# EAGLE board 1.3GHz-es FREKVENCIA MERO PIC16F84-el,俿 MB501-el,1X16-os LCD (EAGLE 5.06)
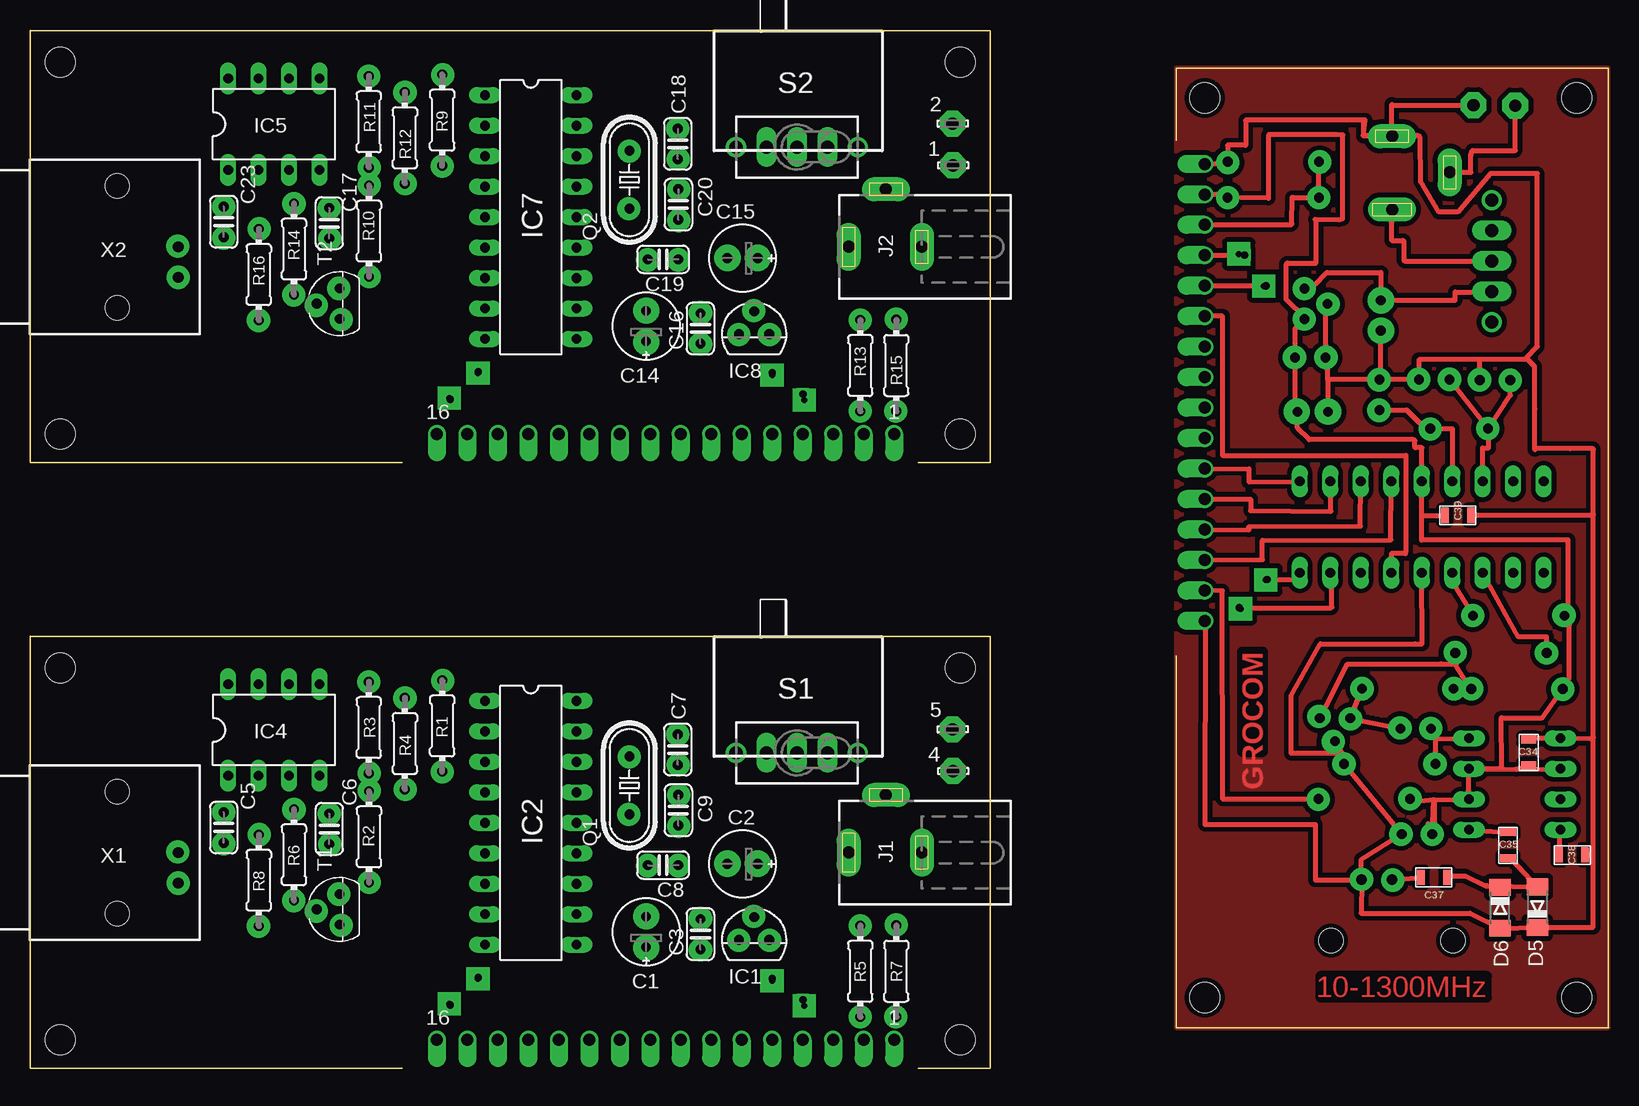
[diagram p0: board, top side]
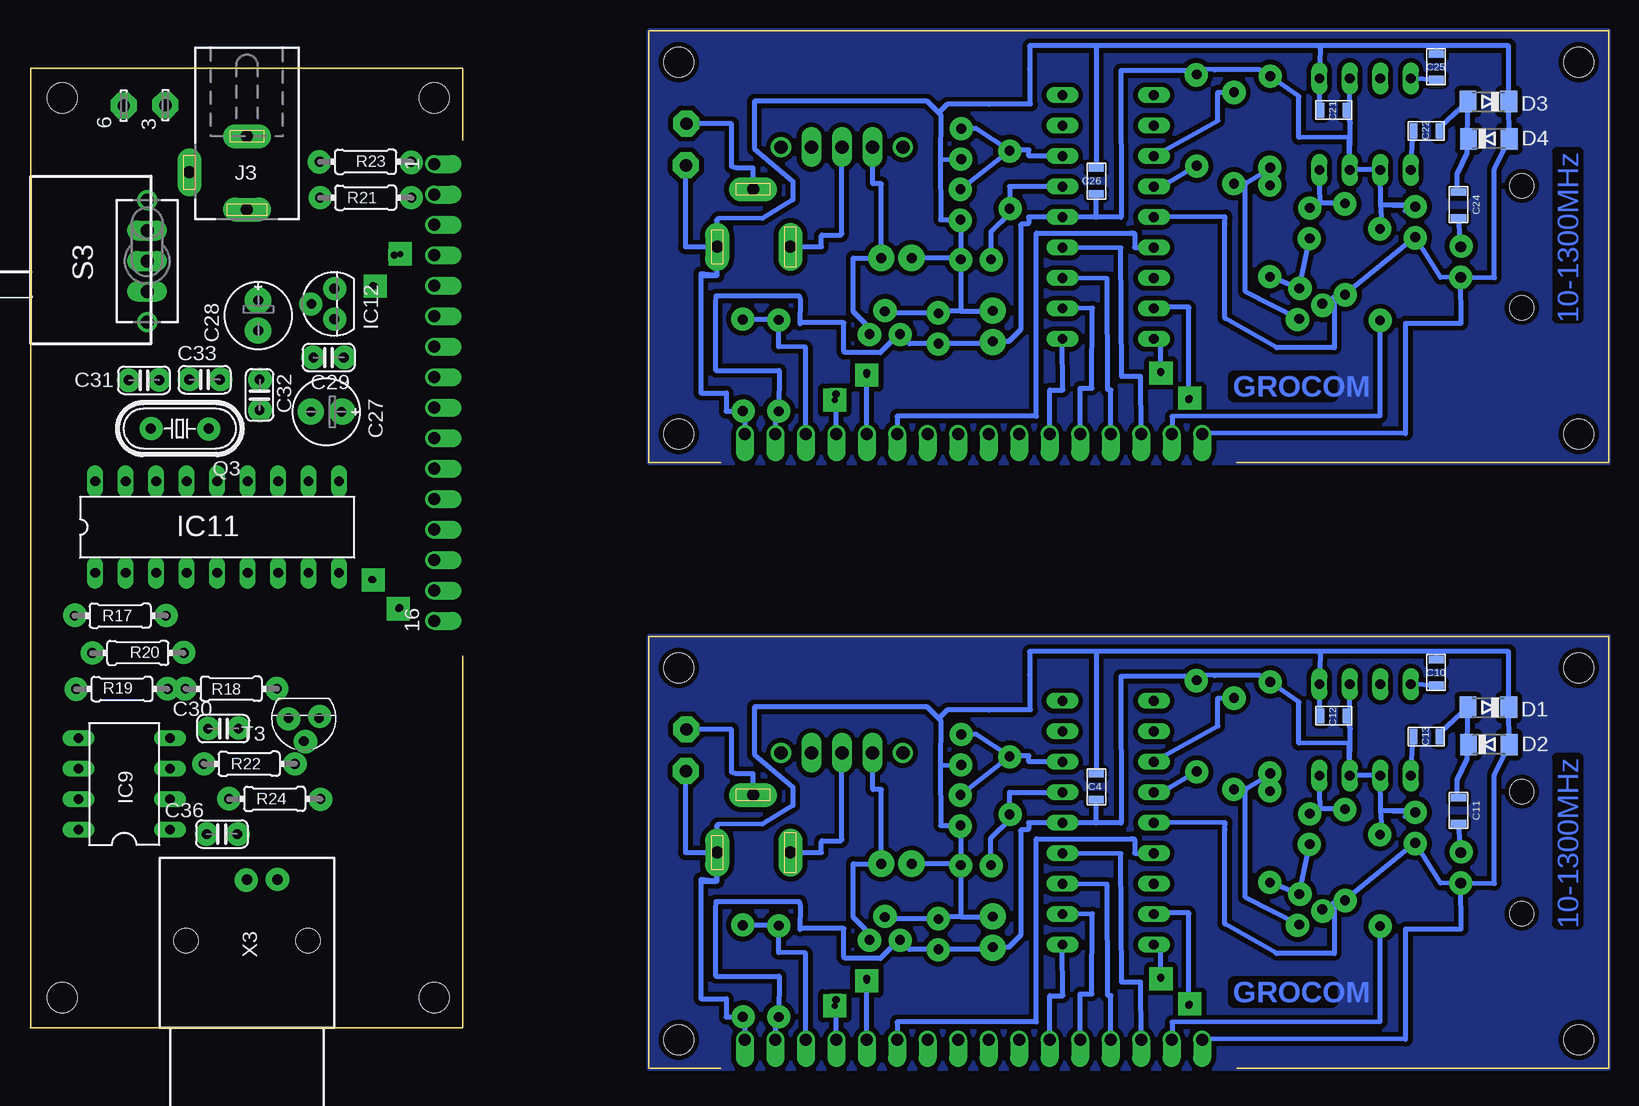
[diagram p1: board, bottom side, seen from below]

Size 131.58 x 86.58 mm. Coordinates in mm from the lower left corner, seen from the top.
Outline: 0,36 0,36.08 0,0
Outline: 0,36 0,0
Outline: 0,36 80,36 80,0 74,0
Outline: 0,0 31,0
Outline: 0,86.5 0,86.58 0,50.5
Outline: 0,86.5 0,50.5
Outline: 0,86.5 80,86.5 80,50.5 74,50.5
Outline: 0,50.5 31,50.5
Outline: 131.5,3.4 131.58,3.4 95.5,3.4
Outline: 131.5,3.4 95.5,3.4
Outline: 131.5,3.4 131.5,83.4 95.5,83.4 95.5,77.4
Outline: 95.5,3.4 95.5,34.4
Copper layers (1*16): Top 0.035mm / dielectric 1.5mm / Bottom 0.035mm
Design rules "default *": minimum track width 10mil, minimum drill 24mil, track to track 8mil, track to pad 8mil, pad to pad 8mil, via to via 8mil, smd to smd 8mil, copper to edge 0mil, drill to drill 8mil, minimum pad ring 10mil, minimum via ring 8mil, stop-mask expansion 4mil, vias tented up to drill 0mil, thermal gap 10mil

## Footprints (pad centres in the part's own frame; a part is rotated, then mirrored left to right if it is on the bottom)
LSP10 = drill 1.016 pad 2.159 octagon: MP 0,0
E2,5-6E = drill 0.813 pad 1.575 round: + -1.27,0 | drill 0.813 pad 1.575 octagon: - 1.27,0
C025-024X044 = drill 0.813 octagon: 1 -1.27,0; 2 1.27,0
0805 = smd 0.635 x 1.27: P$1 1.143,0; P$2 -1.016,0
MINIMELF = smd 1.4 x 1.8: A 1.7,0; C -1.7,0
TO92 = drill 0.813 octagon: 1 -1.27,0; 2 0,1.905; 3 1.27,0
DIL18 = drill 0.813 long: 1 -10.16,-3.81; 2 -7.62,-3.81; 3 -5.08,-3.81; 4 -2.54,-3.81; 5 0,-3.81; 6 2.54,-3.81; 7 5.08,-3.81; 8 7.62,-3.81; 9 10.16,-3.81; 10 10.16,3.81; 11 7.62,3.81; 12 5.08,3.81; 13 2.54,3.81; 14 0,3.81; 15 -2.54,3.81; 16 -5.08,3.81; 17 -7.62,3.81; 18 -10.16,3.81
DMC-162C = drill 1 offset: 1 8,33.5; 2 10.54,33.5; 3 13.08,33.5; 4 15.62,33.5; 5 18.16,33.5; 6 20.7,33.5; 7 23.24,33.5; 8 25.78,33.5; 9 28.32,33.5; 10 30.86,33.5; 11 33.4,33.5; 12 35.94,33.5; 13 38.48,33.5; 14 41.02,33.5; 15 43.56,33.5; 16 46.1,33.5 | hole 2.5: 2.5,2.5; 77.5,2.5; 77.5,33.5; 2.5,33.5
DIL08 = drill 0.813 long: 1 -3.81,-3.81; 2 -1.27,-3.81; 3 1.27,-3.81; 4 3.81,-3.81; 5 3.81,3.81; 6 1.27,3.81; 7 -1.27,3.81; 8 -3.81,3.81
DCJ0202 = drill 1 pad 2 long: 1 0,3.1; 2 4.8,0; 3 0,-3
HC49/S = drill 0.813 round: 1 -2.413,0; 2 2.413,0
0204/7 = drill 0.813 octagon: 1 -3.81,0; 2 3.81,0
TL3XYO = drill 1.1 pad 1.422 long: 1 -2.54,0; 2 0,0; 3 2.54,0 | drill 1.1 pad 1.676 round: M1 -5.08,0; M2 5.08,0
TO92' = drill 0.813 octagon: 1 1.27,0; 2 0,1.905; 3 -1.27,0
AMP_227161 = drill 0.9 pad 1.27 round: 1 0,-5.08; 2 -2.54,-5.08 | hole 2: -5.08,0; 5.08,0

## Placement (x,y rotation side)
1  BE  [LSP10]  76.92,75.29 0 top
2  BE  [LSP10]  76.88,78.78 0 top
3  BE  [LSP10]  120.29,80.32 90 bottom
4  BE  [LSP10]  76.92,24.79 0 top
5  BE  [LSP10]  76.88,28.28 0 top
6  BE  [LSP10]  123.78,80.28 90 bottom
C1  10uF  [E2,5-6E]  51.34,11.39 90 top
C2  10uF  [E2,5-6E]  59.38,17.06 180 top
C3  100nF  [C025-024X044]  55.87,11.19 90 top
C4  1nF  [0805]  42.72,23.55 270 bottom
C5  1nF  [C025-024X044]  16.14,20.08 90 top
C6  10nF  [C025-024X044]  24.94,19.97 270 top
C7  22pF  [C025-024X044]  53.98,26.58 90 top
C8  22pF  [C025-024X044]  52.76,16.95 180 top
C9  CX  [C025-024X044]  54.03,21.53 90 top
C10  1nF  [0805]  14.4,33.08 270 bottom
C11  1nF  [0805]  12.53,21.56 270 bottom
C12  [0805]  23.01,29.4 0 bottom
C13  1nF  [0805]  15.28,27.67 0 bottom
C14  10uF  [E2,5-6E]  51.34,61.89 90 top
C15  10uF  [E2,5-6E]  59.38,67.56 180 top
C16  100nF  [C025-024X044]  55.87,61.69 90 top
C17  10nF  [C025-024X044]  24.94,70.47 270 top
C18  22pF  [C025-024X044]  53.98,77.08 90 top
C19  22pF  [C025-024X044]  52.76,67.45 180 top
C20  CX  [C025-024X044]  54.03,72.03 90 top
C21  [0805]  23.01,79.9 0 bottom
C22  1nF  [0805]  15.28,78.17 0 bottom
C23  1nF  [C025-024X044]  16.14,70.58 90 top
C24  1nF  [0805]  12.53,72.06 270 bottom
C25  1nF  [0805]  14.4,83.58 270 bottom
C26  1nF  [0805]  42.72,74.05 270 bottom
C27  10uF  [E2,5-6E]  106.89,54.74 180 bottom
C28  10uF  [E2,5-6E]  112.56,62.78 270 bottom
C29  100nF  [C025-024X044]  106.69,59.27 180 bottom
C30  10nF  [C025-024X044]  115.47,28.34 0 bottom
C31  22pF  [C025-024X044]  122.08,57.38 180 bottom
C32  22pF  [C025-024X044]  112.45,56.16 270 bottom
C33  CX  [C025-024X044]  117.03,57.43 180 bottom
C34  [0805]  124.9,26.41 270 top
C35  1nF  [0805]  123.17,18.68 270 top
C36  1nF  [C025-024X044]  115.58,19.54 180 bottom
C37  1nF  [0805]  117.06,15.93 180 top
C38  1nF  [0805]  128.58,17.8 180 top
C39  1nF  [0805]  119.05,46.12 180 top
D1  [MINIMELF]  10.05,30.11 180 bottom
D2  [MINIMELF]  10,27 0 bottom
D3  [MINIMELF]  10.05,80.61 180 bottom
D4  [MINIMELF]  10,77.5 0 bottom
D5  [MINIMELF]  125.61,13.45 90 top
D6  [MINIMELF]  122.5,13.4 270 top
IC1  78L05Z  [TO92]  60.34,10.72 0 top
IC2  PIC16F84AP  [DIL18]  41.74,20.48 270 top
IC3  LCD-DMC162C  [DMC-162C]  80.01,35.89 180 top
IC4  [DIL08]  20.32,28.23 0 top
IC5  [DIL08]  20.32,78.73 0 top
IC6  LCD-DMC162C  [DMC-162C]  80.01,86.39 180 top
IC7  PIC16F84AP  [DIL18]  41.74,70.98 270 top
IC8  78L05Z  [TO92]  60.34,61.22 0 top
IC9  [DIL08]  123.73,23.72 90 bottom
IC10  LCD-DMC162C  [DMC-162C]  131.39,83.41 270 bottom
IC11  PIC16F84AP  [DIL18]  115.98,45.14 0 bottom
IC12  78L05Z  [TO92]  106.22,63.74 90 bottom
J1  DCJ0202  [DCJ0202]  71.32,18 90 top
J2  DCJ0202  [DCJ0202]  71.32,68.5 90 top
J3  DCJ0202  [DCJ0202]  113.5,74.72 180 bottom
Q1  [HC49/S]  49.95,23.59 90 top
Q2  [HC49/S]  49.95,74.09 90 top
Q3  [HC49/S]  119.09,53.35 180 bottom
R1  10K  [0204/7]  34.35,28.57 90 top
R2  33K  [0204/7]  28.25,19.31 90 top
R3  470  [0204/7]  28.23,28.42 90 top
R4  470  [0204/7]  31.24,27.09 270 top
R5  10K  [0204/7]  69.19,8.1 90 top
R6  2,2K  [0204/7]  22,17.82 90 top
R7  470  [0204/7]  72.19,8.11 270 top
R8  10-100  [0204/7]  19.07,15.69 90 top
R9  10K  [0204/7]  34.35,79.07 90 top
R10  33K  [0204/7]  28.25,69.81 90 top
R11  470  [0204/7]  28.23,78.92 90 top
R12  470  [0204/7]  31.24,77.59 270 top
R13  10K  [0204/7]  69.19,58.6 90 top
R14  2,2K  [0204/7]  22,68.32 90 top
R15  470  [0204/7]  72.19,58.61 270 top
R16  10-100  [0204/7]  19.07,66.19 90 top
R17  10K  [0204/7]  124.07,37.75 180 bottom
R18  33K  [0204/7]  114.81,31.65 180 bottom
R19  470  [0204/7]  123.92,31.63 180 bottom
R20  470  [0204/7]  122.59,34.64 0 bottom
R21  10K  [0204/7]  103.6,72.59 180 bottom
R22  2,2K  [0204/7]  113.32,25.4 180 bottom
R23  470  [0204/7]  103.61,75.59 0 bottom
R24  10-100  [0204/7]  111.19,22.47 180 bottom
S1  TL32YO  [TL3XYO]  63.91,26.32 180 top
S2  TL32YO  [TL3XYO]  63.91,76.82 180 top
S3  TL32YO  [TL3XYO]  121.82,67.31 270 bottom
T1  BF199  [TO92']  25.8,13.26 90 top
T2  BF199  [TO92']  25.8,63.76 90 top
T3  BF199  [TO92']  108.76,29.2 180 bottom
X1  1-227161-7  [AMP_227161]  7.26,18 90 top
X2  1-227161-7  [AMP_227161]  7.26,68.5 90 top
X3  1-227161-7  [AMP_227161]  113.5,10.66 180 bottom

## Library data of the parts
1-6 = solpad
C1-C3 C5-C9 C14-C20 C23 C27-C33 C36 R1-R24 = rcl
C4 C10-C13 C21 C22 C24-C26 C34 C35 C37-C39 = scenix4
D1-D6 = diode
IC1 IC8 IC12 = Eigene
IC2 IC7 IC11 = microchip
IC3 IC6 IC10 = dodolcd
IC4 IC5 IC9 = MB501
J1-J3 = con-jack
Q1-Q3 = crystal
S1-S3 = switch
T1-T3 = transistor
X1-X3 = con-coax

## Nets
GND: 4.MP C1.- C2.- C3.2 C4.P$2 C5.1 C7.1 C8.1 C9.1 C10.P$2 C12.P$2 D1.C D2.A IC1.2 IC2.5 IC3.1 IC3.16 IC4.5 J1.3 R6.1 R7.2 T1.2 X1.2
GND1: 1.MP C14.- C15.- C16.2 C18.1 C19.1 C20.1 C21.P$2 C23.1 C25.P$2 C26.P$2 D3.C D4.A IC5.5 IC6.1 IC6.16 IC7.5 IC8.2 J2.3 R14.1 R15.2 T2.2 X2.2
GND2: 3.MP C27.- C28.- C29.2 C31.1 C32.1 C33.1 C34.P$2 C36.1 C38.P$2 C39.P$2 D5.C D6.A IC9.5 IC10.1 IC10.16 IC11.5 IC12.2 J3.3 R22.1 R23.2 T3.2 X3.2
N$1: IC2.6 IC3.6
N$2: IC2.8
N$3: IC3.5
N$4: IC2.10 IC3.11
N$5: IC2.11 IC3.12
N$6: IC2.12 IC3.13
N$7: IC2.13 IC3.14
N$8: C1.+ C3.1 C4.P$1 C5.2 C12.P$1 IC1.1 IC2.14 IC3.2 IC4.2 IC4.3 IC4.6 R1.2 R3.2 R5.1 R8.2
N$9: C2.+ IC1.3 S1.3
N$10: R2.2 R3.1 R4.2 T1.3
N$11: C7.2 C9.2 IC2.16 Q1.2
N$12: C8.2 IC2.15 Q1.1
N$13: IC2.4 R1.1
N$14: C6.1 IC4.4 R6.2
N$15: IC3.3 R5.2 R7.1
N$16: IC2.3 R4.1
N$17: C6.2 R2.1 T1.1
N$18: C11.P$2 C13.P$1 D1.A D2.C
N$19: J1.1 S1.2
N$20: C10.P$1 IC4.8
N$21: C13.P$2 IC4.1
N$22: IC3.15 R8.1
N$23: C11.P$1 X1.1
N$24: 5.MP J1.2
N$77: IC6.6 IC7.6
N$78: IC6.11 IC7.10
N$79: IC6.12 IC7.11
N$80: IC6.13 IC7.12
N$81: IC6.14 IC7.13
N$82: C14.+ C16.1 C21.P$1 C23.2 C26.P$1 IC5.2 IC5.3 IC5.6 IC6.2 IC7.14 IC8.1 R9.2 R11.2 R13.1 R16.2
N$83: C15.+ IC8.3 S2.3
N$84: C18.2 C20.2 IC7.16 Q2.2
N$85: C19.2 IC7.15 Q2.1
N$86: IC7.4 R9.1
N$87: IC6.3 R13.2 R15.1
N$88: IC7.3 R12.1
N$89: R10.2 R11.1 R12.2 T2.3
N$90: C17.2 R10.1 T2.1
N$91: C17.1 IC5.4 R14.2
N$92: C22.P$1 C24.P$2 D3.A D4.C
N$93: C24.P$1 X2.1
N$94: C22.P$2 IC5.1
N$95: IC6.15 R16.1
N$96: 2.MP J2.2
N$97: C25.P$1 IC5.8
N$98: J2.1 S2.2
N$151: IC6.5
N$152: IC7.8
N$153: IC10.6 IC11.6
N$154: IC10.11 IC11.10
N$155: IC10.12 IC11.11
N$156: IC10.13 IC11.12
N$157: IC10.14 IC11.13
N$158: C27.+ C29.1 C34.P$1 C36.2 C39.P$1 IC9.2 IC9.3 IC9.6 IC10.2 IC11.14 IC12.1 R17.2 R19.2 R21.1 R24.2
N$159: C28.+ IC12.3 S3.3
N$160: C31.2 C33.2 IC11.16 Q3.2
N$161: C32.2 IC11.15 Q3.1
N$162: IC11.4 R17.1
N$163: IC10.3 R21.2 R23.1
N$164: IC11.3 R20.1
N$165: R18.2 R19.1 R20.2 T3.3
N$166: C30.2 R18.1 T3.1
N$167: C30.1 IC9.4 R22.2
N$168: C35.P$1 C37.P$2 D5.A D6.C
N$169: C37.P$1 X3.1
N$170: C35.P$2 IC9.1
N$171: IC10.15 R24.1
N$172: 6.MP J3.2
N$173: C38.P$1 IC9.8
N$174: J3.1 S3.2
N$227: IC10.5
N$228: IC11.8
S$1: IC7.9
S$2: IC6.4
S$3: IC2.9
S$4: IC3.4
S$6: IC11.9
S$8: IC10.4

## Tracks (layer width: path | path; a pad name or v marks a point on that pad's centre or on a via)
GND
  Bottom 0.406: X1.2 9.54,15.42 9.54,24.48 D2.A D1.C 8.37,34.77 14.39,34.77 | 14.39,34.77 24.07,34.77 24.07,34.58 | 24.07,34.58 IC4.5 24.12,30.23 C12.P$2 | 14.39,34.77 C10.P$2 | X1.2 14.02,15.45 C5.1 R6.1 T1.2 22.88,13.86 22.88,9.59 27.7,9.58 32.01,12.04 32.01,19.92 32,20.5 IC2.5 | IC3.16 33.99,2.47 16.95,2.42 16.95,11.62 12.32,11.62 X1.2 | 55.7,25.27 C7.1 | 55.7,25.27 55.7,20.25 C9.1 C8.1 | 42.76,34.78 24.17,34.77 24.07,34.58 | 55.7,25.27 55.7,29.03 55.84,29.17 | C8.1 54.13,17.06 C2.- | C4.P$2 42.72,24.6 42.72,24.61 42.72,34.73 42.76,34.78 | 54,12.66 C1.- | 54,12.66 55.68,12.66 C3.2 60.19,12.46 IC1.2 | C8.1 54.03,12.68 54,12.66 | IC3.1 72.01,3.95 R7.2 73.54,4.3 73.57,4.27 73.57,5.78 73.54,5.81 75.65,5.81 75.68,5.84 75.68,15.75 | 75.68,15.75 75.63,15.61 74.38,15.61 74.36,15.68 J1.3 74.33,17.98 76.97,17.98 76.92,18.04 4.MP | 42.76,34.78 48.23,34.78 48.27,34.73 48.27,32.82 48.27,32.81 48.27,29.94 48.19,29.9 51.59,29.9 51.64,29.88 55.13,29.88 55.84,29.17 | 75.68,15.75 74.33,15.62 74.35,15.68 74.35,20.22 74.23,20.34 70.53,20.39 68.01,21.91 68.01,23.47 71.21,26.19 71.21,30.12 56.79,30.12 55.84,29.17
GND1
  Bottom 0.406: X2.2 9.54,65.92 9.54,74.98 D4.A D3.C 8.37,85.27 14.39,85.27 | 14.39,85.27 24.07,85.27 24.07,85.08 | 24.07,85.08 IC5.5 24.12,80.73 C21.P$2 | 14.39,85.27 C25.P$2 | X2.2 14.02,65.95 C23.1 R14.1 T2.2 22.88,64.36 22.88,60.09 27.7,60.08 32.01,62.54 32.01,70.42 32,71 IC7.5 | IC6.16 33.99,52.97 16.95,52.92 16.95,62.12 12.32,62.12 X2.2 | 55.7,75.77 C18.1 | 55.7,75.77 55.7,70.75 C20.1 C19.1 | 42.76,85.28 24.17,85.28 24.07,85.08 | 55.7,75.77 55.7,79.53 55.84,79.67 | C19.1 54.13,67.56 C15.- | C26.P$2 42.72,75.1 42.72,75.11 42.72,85.23 42.76,85.28 | 54,63.16 C14.- | 54,63.16 55.68,63.16 C16.2 60.19,62.96 IC8.2 | C19.1 54.03,63.18 54,63.16 | IC6.1 72.01,54.45 R15.2 73.54,54.8 73.57,54.77 73.57,56.28 73.54,56.31 75.65,56.31 75.68,56.34 75.68,66.25 | 75.68,66.25 75.63,66.11 74.38,66.11 74.36,66.18 J2.3 74.33,68.48 76.97,68.48 76.92,68.54 1.MP | 42.76,85.28 48.23,85.28 48.27,85.23 48.27,83.32 48.27,83.31 48.27,80.44 48.19,80.4 51.59,80.4 51.64,80.38 55.13,80.38 55.84,79.67 | 75.68,66.25 74.33,66.11 74.35,66.18 74.35,70.72 74.23,70.84 70.53,70.89 68.01,72.41 68.01,73.97 71.21,76.69 71.21,80.62 56.79,80.62 55.84,79.67
GND2
  Top 0.406: X3.2 110.92,12.95 119.98,12.95 D6.A D5.C 130.27,11.77 130.27,17.79 | 130.27,17.79 130.27,27.47 130.08,27.47 | 130.08,27.47 IC9.5 125.73,27.52 C34.P$2 | 130.27,17.79 C38.P$2 | X3.2 110.95,17.42 C36.1 R22.1 T3.2 109.36,26.28 105.09,26.28 105.08,31.1 107.54,35.41 115.42,35.41 116,35.4 IC11.5 | IC10.16 97.97,37.39 97.92,20.35 107.12,20.35 107.12,15.72 X3.2 | 120.77,59.1 C31.1 | 120.77,59.1 115.75,59.1 C33.1 C32.1 | 130.28,46.16 130.28,27.57 130.08,27.47 | 120.77,59.1 124.53,59.1 124.67,59.24 | C32.1 112.56,57.53 C28.- | C39.P$2 120.1,46.12 120.11,46.12 130.23,46.12 130.28,46.16 | 108.16,57.4 C27.- | 108.16,57.4 108.16,59.08 C29.2 107.96,63.59 IC12.2 | C32.1 108.18,57.43 108.16,57.4 | IC10.1 99.45,75.41 R23.2 99.8,76.94 99.77,76.97 101.28,76.97 101.31,76.94 101.31,79.05 101.34,79.08 111.25,79.08 | 111.25,79.08 111.11,79.03 111.11,77.78 111.18,77.76 J3.3 113.48,77.73 113.48,80.37 113.54,80.32 3.MP | 130.28,46.16 130.28,51.63 130.23,51.67 128.32,51.67 128.31,51.67 125.44,51.67 125.4,51.59 125.4,54.98 125.38,55.04 125.38,58.53 124.67,59.24 | 111.25,79.08 111.11,77.72 111.18,77.75 115.72,77.75 115.84,77.64 115.89,73.93 117.41,71.41 118.97,71.41 121.69,74.61 125.62,74.61 125.62,60.19 124.67,59.24
N$1
  Bottom 0.406: IC2.6 39.53,17.94 39.53,19.12 39.76,19.16 39.71,19.16 47.72,19.16 47.72,3.89 59.31,3.89 IC3.6
N$2  (via drill 0.6)
  Bottom 0.406: IC2.8 37.92,12.97 37.91,12.98 35.06,12.98 35.01,12.93 v35.01,5.28
N$3  (via drill 0.6)
  Top 0.406: v61.85,7.5 61.8,7.55
  Bottom 0.406: v61.85,7.5 IC3.5
N$4
  Bottom 0.406: IC2.10 45.51,6.06 46.59,6.06 IC3.11
N$5
  Bottom 0.406: IC2.11 43.05,12.9 43.1,6.22 44.07,6.22 IC3.12
N$6
  Bottom 0.406: IC2.12 41.82,15.36 41.77,6.06 41.51,6.06 IC3.13
N$7
  Bottom 0.406: IC2.13 40.67,17.9 40.62,7.2 39.03,7.2 IC3.14
N$8
  Bottom 0.406: IC4.3 IC4.2 19.01,21.46 C5.2 17,21 16.21,21.51 19.03,21.51 18.89,20.02 R8.2 | IC4.3 21.55,28.34 | 21.55,28.34 IC4.6 | 21.55,28.34 C12.P$1 | IC4.3 21.64,27.15 25.84,27.12 25.84,30.54 R3.2 29.1,32.76 32.87,32.75 34.16,32.81 R1.2 34.46,32.67 40.66,32.68 40.65,20.46 42.77,20.47 | 42.77,20.47 IC2.14 48.35,20.48 48.35,20.49 48.35,19.95 48.4,19.91 48.94,19.91 49.03,19.81 49.03,11.09 50.01,10.12 C1.+ 51.53,9.92 C3.1 58.28,9.92 IC1.1 59.2,10.71 60.71,9.17 63.68,9.2 63.76,9.29 63.76,11.67 67.31,11.67 67.4,11.59 67.36,13.57 67.45,13.89 74.42,13.91 74.46,13.32 74.46,7.74 74.37,7.7 69.15,7.7 R5.1 69.47,4.02 IC3.2 | C4.P$1 42.72,20.52 42.77,20.47
N$9
  Bottom 0.406: IC1.3 61.96,11.06 61.96,11.59 62.95,12.58 62.95,17.09 62.92,17.06 C2.+ 60.65,23.26 60.64,23.27 61.33,23.27 61.33,26.28 S1.3
N$10
  Bottom 0.406: R3.1 R2.2 28.46,24.39 30.16,23.33 R4.2 30.33,23.36 30.33,22.1 30.3,14.28 T1.3
N$11
  Bottom 0.406: IC2.16 48.34,25.56 48.34,26.06 49.95,26.06 Q1.2 | Q1.2 52.73,27.86 C7.2 | Q1.2 C9.2
N$12
  Bottom 0.406: IC2.15 49.95,23.02 Q1.1 49.95,20.78 51.5,19.23 51.5,16.96 C8.2
N$13
  Bottom 0.406: R1.1 36.65,23.37 IC2.4
N$14
  Bottom 0.406: R6.2 24.07,21.63 | 24.07,21.63 IC4.4 | 24.07,21.63 C6.1
N$15
  Bottom 0.406: R7.1 R5.2 69.19,11.8 69.2,11.79 69.2,9.78 69.21,9.68 67.02,9.65 66.95,9.58 66.95,2.41 IC3.3
N$16
  Bottom 0.406: IC2.3 32.59,28.53 32.58,30.89 R4.1
N$17
  Bottom 0.406: C6.2 T1.1 R2.1
N$18
  Bottom 0.406: C11.P$2 12.64,22.5 12.64,24.07 11.83,25.79 11.83,25.93 | 11.83,25.93 D1.A 14,28 14.11,27.79 C13.P$1 | 11.83,25.93 D2.C
N$19
  Bottom 0.406: S1.2 63.91,19.07 63.99,19 65.56,19 65.64,18.92 65.64,17.98 68.2,17.98 J1.1
N$20
  Bottom 0.406: C10.P$1 IC4.8
N$21
  Bottom 0.406: IC4.1 C13.P$2
N$22
  Bottom 0.406: R8.1 19.06,3.9 36.41,3.86 IC3.15
N$23
  Bottom 0.406: X1.1 C11.P$1
N$24
  Bottom 0.406: 5.MP 73.15,28.28 73.12,28.25 73.12,24.69 72.74,24.58 71.32,24.58 J1.2
N$25  (via drill 0.5 pad 2.18)
  other vias: 51.35,10.07
N$26  (via drill 0.5 pad 2.18)
  other vias: 51.35,12.67
N$27  (via drill 0.5 pad 2.18)
  other vias: 58.13,17.08
N$28  (via drill 0.5 pad 2.18)
  other vias: 60.64,17.08
N$29  (via drill 0.5 pad 1.93)
  other vias: 59.07,10.7
N$30  (via drill 0.5 pad 1.93)
  other vias: 60.32,12.67
N$31  (via drill 0.5 pad 1.93)
  other vias: 61.62,10.7
N$32  (via drill 0.5 pad 1.93)
  other vias: 51.47,16.92
N$33  (via drill 0.5 pad 1.93)
  other vias: 54.01,16.92
N$34  (via drill 0.5 pad 1.93)
  other vias: 55.88,12.5
N$35  (via drill 0.5 pad 1.93)
  other vias: 55.88,9.88
N$36  (via drill 0.5 pad 1.93)
  other vias: 69.19,11.9
N$37  (via drill 0.5 pad 1.93)
  other vias: 72.18,11.98
N$38  (via drill 0.5 pad 1.93)
  other vias: 69.19,4.3
N$39  (via drill 0.5 pad 1.93)
  other vias: 72.14,4.3
N$40  (via drill 0.5 pad 1.93)
  other vias: 53.97,27.84
N$41  (via drill 0.5 pad 1.93)
  other vias: 54.01,25.3
N$42  (via drill 0.5 pad 1.93)
  other vias: 54.05,22.79
N$43  (via drill 0.5 pad 1.93)
  other vias: 54.05,20.21
N$44  (via drill 0.5 pad 1.93)
  other vias: 49.9,21.18
N$45  (via drill 0.5 pad 1.93)
  other vias: 49.94,25.97
N$46  (via drill 0.5 pad 1.93)
  other vias: 34.39,32.33
N$47  (via drill 0.5 pad 1.93)
  other vias: 31.25,30.87
N$48  (via drill 0.5 pad 1.93)
  other vias: 28.22,32.22
N$49  (via drill 0.5 pad 1.93)
  other vias: 28.26,24.62
N$50  (via drill 0.5 pad 1.93)
  other vias: 28.26,23.16
N$51  (via drill 0.5 pad 1.93)
  other vias: 31.27,23.26
N$52  (via drill 0.5 pad 1.93)
  other vias: 34.36,24.72
N$53  (via drill 0.5 pad 1.93)
  other vias: 22,21.58
N$54  (via drill 0.5 pad 1.93)
  other vias: 24.94,21.22
N$55  (via drill 0.5 pad 1.93)
  other vias: 24.99,18.67
N$56  (via drill 0.5 pad 1.93)
  other vias: 28.26,15.5
N$57  (via drill 0.5 pad 1.93)
  other vias: 25.74,14.54
N$58  (via drill 0.5 pad 1.93)
  other vias: 23.85,13.11
N$59  (via drill 0.5 pad 1.93)
  other vias: 25.95,11.92
N$60  (via drill 0.5 pad 1.93)
  other vias: 21.98,14
N$61  (via drill 0.5 pad 1.93)
  other vias: 19.05,11.87
N$62  (via drill 0.5 pad 1.93)
  other vias: 19.1,19.5
N$63  (via drill 0.5 pad 1.93)
  other vias: 16.14,18.75
N$64  (via drill 0.5 pad 1.93)
  other vias: 16.14,21.35
N$65  (via drill 0.5 pad 1.93)
  other vias: 12.3,18.05
N$66  (via drill 0.5 pad 1.93)
  other vias: 12.36,15.45
N$67  (via drill 0.5 pad 1.93)
  other vias: 61.84,7.3
N$68  (via drill 0.5 pad 1.93)
  other vias: 64.51,5.23
N$69  (via drill 0.5 pad 1.93)
  other vias: 37.33,7.49
N$70  (via drill 0.5 pad 1.93)
  other vias: 34.93,5.38
N$71  (via drill 0.5 pad 1.93)
  other vias: 2.51,33.4
N$72  (via drill 0.5 pad 1.93)
  other vias: 2.54,2.39
N$73  (via drill 0.5 pad 1.93)
  other vias: 77.52,2.36
N$74  (via drill 0.5 pad 1.93)
  other vias: 77.56,33.41
N$75  (via drill 0.5 pad 1.93)
  other vias: 7.29,12.93
N$76  (via drill 0.5 pad 1.93)
  other vias: 7.23,23.09
N$77
  Bottom 0.406: IC7.6 39.53,68.44 39.53,69.62 39.76,69.66 39.71,69.66 47.72,69.66 47.72,54.39 59.31,54.39 IC6.6
N$78
  Bottom 0.406: IC7.10 45.51,56.56 46.59,56.56 IC6.11
N$79
  Bottom 0.406: IC7.11 43.05,63.4 43.1,56.72 44.07,56.72 IC6.12
N$80
  Bottom 0.406: IC7.12 41.82,65.86 41.77,56.56 41.51,56.56 IC6.13
N$81
  Bottom 0.406: IC7.13 40.67,68.4 40.62,57.7 39.03,57.7 IC6.14
N$82
  Bottom 0.406: IC5.3 IC5.2 19.01,71.96 C23.2 17,71.5 16.21,72 19.03,72 18.89,70.53 R16.2 | IC5.3 21.55,78.84 | 21.55,78.84 IC5.6 | 21.55,78.84 C21.P$1 | IC5.3 21.64,77.65 25.84,77.62 25.84,81.04 R11.2 29.1,83.26 32.87,83.25 34.16,83.31 R9.2 34.46,83.17 40.66,83.18 40.65,70.97 42.77,70.97 | 42.77,70.97 IC7.14 48.35,70.98 48.35,70.99 48.35,70.45 48.4,70.41 48.94,70.41 49.03,70.31 49.03,61.59 50.01,60.62 C14.+ 51.53,60.42 C16.1 58.28,60.42 IC8.1 59.2,61.22 60.71,59.67 63.68,59.7 63.76,59.79 63.76,62.17 67.31,62.17 67.4,62.09 67.36,64.07 67.45,64.39 74.42,64.41 74.46,63.82 74.46,58.24 74.37,58.2 69.15,58.2 R13.1 69.47,54.52 IC6.2 | C26.P$1 42.72,71.02 42.77,70.97
N$83
  Bottom 0.406: IC8.3 61.96,61.56 61.96,62.09 62.95,63.08 62.95,67.59 62.92,67.56 C15.+ 60.65,73.76 60.64,73.76 61.33,73.76 61.33,76.78 S2.3
N$84
  Bottom 0.406: IC7.16 48.34,76.06 48.34,76.56 49.95,76.56 Q2.2 | Q2.2 52.73,78.36 C18.2 | Q2.2 C20.2
N$85
  Bottom 0.406: IC7.15 49.95,73.52 Q2.1 49.95,71.28 51.5,69.73 51.5,67.46 C19.2
N$86
  Bottom 0.406: R9.1 36.65,73.87 IC7.4
N$87
  Bottom 0.406: R15.1 R13.2 69.19,62.3 69.2,62.29 69.2,60.28 69.21,60.18 67.02,60.15 66.95,60.08 66.95,52.91 IC6.3
N$88
  Bottom 0.406: IC7.3 32.59,79.03 32.58,81.39 R12.1
N$89
  Bottom 0.406: R11.1 R10.2 28.46,74.89 30.16,73.83 R12.2 30.33,73.86 30.33,72.6 30.3,64.78 T2.3
N$90
  Bottom 0.406: C17.2 T2.1 R10.1
N$91
  Bottom 0.406: R14.2 24.07,72.13 | 24.07,72.13 IC5.4 | 24.07,72.13 C17.1
N$92
  Bottom 0.406: C24.P$2 12.64,73 12.64,74.58 11.83,76.29 11.83,76.43 | 11.83,76.43 D3.A 14,78.5 14.11,78.29 C22.P$1 | 11.83,76.43 D4.C
N$93
  Bottom 0.406: X2.1 C24.P$1
N$94
  Bottom 0.406: IC5.1 C22.P$2
N$95
  Bottom 0.406: R16.1 19.06,54.4 36.41,54.36 IC6.15
N$96
  Bottom 0.406: 2.MP 73.15,78.78 73.12,78.75 73.12,75.19 72.74,75.08 71.32,75.08 J2.2
N$97
  Bottom 0.406: C25.P$1 IC5.8
N$98
  Bottom 0.406: S2.2 63.91,69.57 63.99,69.5 65.56,69.5 65.64,69.42 65.64,68.48 68.2,68.48 J2.1
N$99  (via drill 0.5 pad 2.18)
  other vias: 51.35,60.57
N$100  (via drill 0.5 pad 2.18)
  other vias: 51.35,63.17
N$101  (via drill 0.5 pad 2.18)
  other vias: 58.13,67.58
N$102  (via drill 0.5 pad 2.18)
  other vias: 60.64,67.58
N$103  (via drill 0.5 pad 1.93)
  other vias: 59.07,61.2
N$104  (via drill 0.5 pad 1.93)
  other vias: 60.32,63.17
N$105  (via drill 0.5 pad 1.93)
  other vias: 61.62,61.2
N$106  (via drill 0.5 pad 1.93)
  other vias: 51.47,67.42
N$107  (via drill 0.5 pad 1.93)
  other vias: 54.01,67.42
N$108  (via drill 0.5 pad 1.93)
  other vias: 55.88,63
N$109  (via drill 0.5 pad 1.93)
  other vias: 55.88,60.38
N$110  (via drill 0.5 pad 1.93)
  other vias: 69.19,62.4
N$111  (via drill 0.5 pad 1.93)
  other vias: 72.18,62.48
N$112  (via drill 0.5 pad 1.93)
  other vias: 69.19,54.8
N$113  (via drill 0.5 pad 1.93)
  other vias: 72.14,54.8
N$114  (via drill 0.5 pad 1.93)
  other vias: 53.97,78.34
N$115  (via drill 0.5 pad 1.93)
  other vias: 54.01,75.8
N$116  (via drill 0.5 pad 1.93)
  other vias: 54.05,73.29
N$117  (via drill 0.5 pad 1.93)
  other vias: 54.05,70.71
N$118  (via drill 0.5 pad 1.93)
  other vias: 49.9,71.68
N$119  (via drill 0.5 pad 1.93)
  other vias: 49.94,76.47
N$120  (via drill 0.5 pad 1.93)
  other vias: 34.39,82.83
N$121  (via drill 0.5 pad 1.93)
  other vias: 31.25,81.37
N$122  (via drill 0.5 pad 1.93)
  other vias: 28.22,82.72
N$123  (via drill 0.5 pad 1.93)
  other vias: 28.26,75.12
N$124  (via drill 0.5 pad 1.93)
  other vias: 28.26,73.66
N$125  (via drill 0.5 pad 1.93)
  other vias: 31.27,73.76
N$126  (via drill 0.5 pad 1.93)
  other vias: 34.36,75.22
N$127  (via drill 0.5 pad 1.93)
  other vias: 22,72.08
N$128  (via drill 0.5 pad 1.93)
  other vias: 24.94,71.72
N$129  (via drill 0.5 pad 1.93)
  other vias: 24.99,69.17
N$130  (via drill 0.5 pad 1.93)
  other vias: 28.26,66
N$131  (via drill 0.5 pad 1.93)
  other vias: 25.74,65.04
N$132  (via drill 0.5 pad 1.93)
  other vias: 23.85,63.61
N$133  (via drill 0.5 pad 1.93)
  other vias: 25.95,62.42
N$134  (via drill 0.5 pad 1.93)
  other vias: 21.98,64.5
N$135  (via drill 0.5 pad 1.93)
  other vias: 19.05,62.37
N$136  (via drill 0.5 pad 1.93)
  other vias: 19.1,70
N$137  (via drill 0.5 pad 1.93)
  other vias: 16.14,69.25
N$138  (via drill 0.5 pad 1.93)
  other vias: 16.14,71.85
N$139  (via drill 0.5 pad 1.93)
  other vias: 12.3,68.55
N$140  (via drill 0.5 pad 1.93)
  other vias: 12.36,65.95
N$141  (via drill 0.5 pad 1.93)
  other vias: 61.84,57.8
N$142  (via drill 0.5 pad 1.93)
  other vias: 64.51,55.73
N$143  (via drill 0.5 pad 1.93)
  other vias: 37.33,57.99
N$144  (via drill 0.5 pad 1.93)
  other vias: 34.93,55.88
N$145  (via drill 0.5 pad 1.93)
  other vias: 2.51,83.9
N$146  (via drill 0.5 pad 1.93)
  other vias: 2.54,52.89
N$147  (via drill 0.5 pad 1.93)
  other vias: 77.52,52.86
N$148  (via drill 0.5 pad 1.93)
  other vias: 77.56,83.91
N$149  (via drill 0.5 pad 1.93)
  other vias: 7.29,63.43
N$150  (via drill 0.5 pad 1.93)
  other vias: 7.23,73.59
N$151  (via drill 0.6)
  Top 0.406: v61.85,58 61.8,58.05
  Bottom 0.406: v61.85,58 IC6.5
N$152  (via drill 0.6)
  Bottom 0.406: IC7.8 37.92,63.47 37.91,63.48 35.06,63.48 35.01,63.43 v35.01,55.78
N$153
  Top 0.406: IC11.6 113.44,42.93 114.62,42.93 114.66,43.16 114.66,43.11 114.66,51.12 99.39,51.12 99.39,62.71 IC10.6
N$154
  Top 0.406: IC11.10 101.56,48.91 101.56,49.99 IC10.11
N$155
  Top 0.406: IC11.11 108.4,46.45 101.72,46.5 101.72,47.47 IC10.12
N$156
  Top 0.406: IC11.12 110.86,45.22 101.56,45.16 101.56,44.91 IC10.13
N$157
  Top 0.406: IC11.13 113.4,44.07 102.7,44.02 102.7,42.43 IC10.14
N$158
  Top 0.406: IC9.3 IC9.2 116.96,22.41 C36.2 116.5,20.4 117,19.61 117,22.43 115.53,22.29 R24.2 | IC9.3 123.84,24.95 | 123.84,24.95 IC9.6 | 123.84,24.95 C34.P$1 | IC9.3 122.65,25.05 122.62,29.24 126.04,29.24 R19.2 128.26,32.5 128.25,36.27 128.31,37.56 R17.2 128.17,37.86 128.18,44.06 115.97,44.05 115.97,46.16 | 115.97,46.16 IC11.14 115.98,51.75 115.99,51.76 115.45,51.76 115.41,51.8 115.41,52.34 115.31,52.43 106.59,52.43 105.62,53.41 C27.+ 105.42,54.94 C29.1 105.42,61.68 IC12.1 106.22,62.6 104.67,64.11 104.7,67.08 104.79,67.16 107.17,67.16 107.17,70.71 107.09,70.8 109.07,70.76 109.39,70.85 109.41,77.82 108.82,77.86 103.24,77.86 103.2,77.77 103.2,72.55 R21.1 99.52,72.87 IC10.2 | C39.P$1 116.02,46.12 115.97,46.16
N$159
  Top 0.406: IC12.3 106.56,65.36 107.09,65.36 108.08,66.36 112.59,66.36 112.56,66.32 C28.+ 118.76,64.05 118.76,64.04 118.76,64.73 121.78,64.73 S3.3
N$160
  Top 0.406: IC11.16 121.06,51.74 121.56,51.74 121.56,53.35 Q3.2 | Q3.2 123.36,56.13 C31.2 | Q3.2 C33.2
N$161
  Top 0.406: IC11.15 118.52,53.35 Q3.1 116.28,53.35 114.73,54.9 112.46,54.9 C32.2
N$162
  Top 0.406: R17.1 118.87,40.05 IC11.4
N$163
  Top 0.406: R23.1 R21.2 107.3,72.59 107.29,72.6 105.28,72.6 105.18,72.61 105.15,70.42 105.08,70.35 97.91,70.35 IC10.3
N$164
  Top 0.406: IC11.3 124.03,35.99 126.39,35.98 R20.1
N$165
  Top 0.406: R19.1 R18.2 119.89,31.86 118.83,33.56 R20.2 118.86,33.73 117.6,33.73 109.78,33.7 T3.3
N$166
  Top 0.406: C30.2 T3.1 R18.1
N$167
  Top 0.406: R22.2 117.13,27.47 | 117.13,27.47 IC9.4 | 117.13,27.47 C30.1
N$168
  Top 0.406: C37.P$2 118,16.05 119.58,16.05 121.29,15.23 121.43,15.23 | 121.43,15.23 D5.A 123.5,17.4 123.29,17.51 C35.P$1 | 121.43,15.23 D6.C
N$169
  Top 0.406: X3.1 C37.P$1
N$170
  Top 0.406: IC9.1 C35.P$2
N$171
  Top 0.406: R24.1 99.4,22.46 99.36,39.81 IC10.15
N$172
  Top 0.406: 6.MP 123.78,76.55 123.75,76.52 120.19,76.52 120.08,76.14 120.08,74.72 J3.2
N$173
  Top 0.406: C38.P$1 IC9.8
N$174
  Top 0.406: S3.2 114.57,67.31 114.5,67.39 114.5,68.96 114.42,69.03 113.48,69.03 113.48,71.6 J3.1
N$175  (via drill 0.5 pad 2.18)
  other vias: 105.57,54.75
N$176  (via drill 0.5 pad 2.18)
  other vias: 108.17,54.75
N$177  (via drill 0.5 pad 2.18)
  other vias: 112.58,61.53
N$178  (via drill 0.5 pad 2.18)
  other vias: 112.58,64.04
N$179  (via drill 0.5 pad 1.93)
  other vias: 106.2,62.47
N$180  (via drill 0.5 pad 1.93)
  other vias: 108.17,63.72
N$181  (via drill 0.5 pad 1.93)
  other vias: 106.2,65.02
N$182  (via drill 0.5 pad 1.93)
  other vias: 112.42,54.87
N$183  (via drill 0.5 pad 1.93)
  other vias: 112.42,57.41
N$184  (via drill 0.5 pad 1.93)
  other vias: 108,59.28
N$185  (via drill 0.5 pad 1.93)
  other vias: 105.38,59.28
N$186  (via drill 0.5 pad 1.93)
  other vias: 107.4,72.59
N$187  (via drill 0.5 pad 1.93)
  other vias: 107.48,75.58
N$188  (via drill 0.5 pad 1.93)
  other vias: 99.8,72.59
N$189  (via drill 0.5 pad 1.93)
  other vias: 99.8,75.54
N$190  (via drill 0.5 pad 1.93)
  other vias: 123.34,57.37
N$191  (via drill 0.5 pad 1.93)
  other vias: 120.8,57.41
N$192  (via drill 0.5 pad 1.93)
  other vias: 118.29,57.45
N$193  (via drill 0.5 pad 1.93)
  other vias: 115.71,57.45
N$194  (via drill 0.5 pad 1.93)
  other vias: 116.68,53.3
N$195  (via drill 0.5 pad 1.93)
  other vias: 121.47,53.34
N$196  (via drill 0.5 pad 1.93)
  other vias: 127.83,37.79
N$197  (via drill 0.5 pad 1.93)
  other vias: 126.37,34.65
N$198  (via drill 0.5 pad 1.93)
  other vias: 127.72,31.62
N$199  (via drill 0.5 pad 1.93)
  other vias: 120.12,31.66
N$200  (via drill 0.5 pad 1.93)
  other vias: 118.66,31.66
N$201  (via drill 0.5 pad 1.93)
  other vias: 118.76,34.67
N$202  (via drill 0.5 pad 1.93)
  other vias: 120.22,37.76
N$203  (via drill 0.5 pad 1.93)
  other vias: 117.08,25.4
N$204  (via drill 0.5 pad 1.93)
  other vias: 116.72,28.34
N$205  (via drill 0.5 pad 1.93)
  other vias: 114.17,28.39
N$206  (via drill 0.5 pad 1.93)
  other vias: 111,31.66
N$207  (via drill 0.5 pad 1.93)
  other vias: 110.04,29.14
N$208  (via drill 0.5 pad 1.93)
  other vias: 108.61,27.25
N$209  (via drill 0.5 pad 1.93)
  other vias: 107.42,29.35
N$210  (via drill 0.5 pad 1.93)
  other vias: 109.5,25.38
N$211  (via drill 0.5 pad 1.93)
  other vias: 107.37,22.45
N$212  (via drill 0.5 pad 1.93)
  other vias: 115,22.5
N$213  (via drill 0.5 pad 1.93)
  other vias: 114.25,19.54
N$214  (via drill 0.5 pad 1.93)
  other vias: 116.85,19.54
N$215  (via drill 0.5 pad 1.93)
  other vias: 113.55,15.71
N$216  (via drill 0.5 pad 1.93)
  other vias: 110.95,15.76
N$217  (via drill 0.5 pad 1.93)
  other vias: 102.81,65.24
N$218  (via drill 0.5 pad 1.93)
  other vias: 100.73,67.91
N$219  (via drill 0.5 pad 1.93)
  other vias: 102.99,40.73
N$220  (via drill 0.5 pad 1.93)
  other vias: 100.88,38.33
N$221  (via drill 0.5 pad 1.93)
  other vias: 128.9,5.91
N$222  (via drill 0.5 pad 1.93)
  other vias: 97.89,5.94
N$223  (via drill 0.5 pad 1.93)
  other vias: 97.86,80.92
N$224  (via drill 0.5 pad 1.93)
  other vias: 128.91,80.96
N$225  (via drill 0.5 pad 1.93)
  other vias: 108.43,10.69
N$226  (via drill 0.5 pad 1.93)
  other vias: 118.59,10.63
N$227  (via drill 0.6)
  Top 0.406: v103,65.25 IC10.5
  Bottom 0.406: v103,65.25 103.05,65.2
N$228  (via drill 0.6)
  Top 0.406: IC11.8 108.47,41.33 108.48,41.31 108.48,38.46 108.43,38.41 v100.78,38.41
S$1  (via drill 0.6)
  Bottom 0.406: IC7.9 37.46,60.82 37.36,60.77 v37.36,58.08
S$2  (via drill 0.6)
  Top 0.406: v64.41,56.22 64.36,55.81
  Bottom 0.406: v64.41,56.22 64.41,52.91 IC6.4
S$3  (via drill 0.6)
  Bottom 0.406: IC2.9 37.46,10.32 37.36,10.28 v37.36,7.58
S$4  (via drill 0.6)
  Top 0.406: v64.41,5.71 64.36,5.31
  Bottom 0.406: v64.41,5.71 64.41,2.41 IC3.4
S$5
  pour Bottom (isolate 0.406): 0,86.5 80,86.5 80,50.5 0,50.5
S$6  (via drill 0.6)
  Top 0.406: IC11.9 105.82,40.86 105.78,40.76 v103.08,40.76
S$7
  pour Bottom (isolate 0.406): 0,36 80,36 80,0 0,0
S$8  (via drill 0.6)
  Top 0.406: v101.22,67.81 97.91,67.81 IC10.4
  Bottom 0.406: v101.22,67.81 100.81,67.76
S$9
  pour Top (isolate 0.406): 131.5,3.4 131.5,83.4 95.5,83.4 95.5,3.4

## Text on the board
Top: GROCOM | 10-1300MHz
Bottom: 10-1300MHz | GROCOM | 10-1300MHz | GROCOM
